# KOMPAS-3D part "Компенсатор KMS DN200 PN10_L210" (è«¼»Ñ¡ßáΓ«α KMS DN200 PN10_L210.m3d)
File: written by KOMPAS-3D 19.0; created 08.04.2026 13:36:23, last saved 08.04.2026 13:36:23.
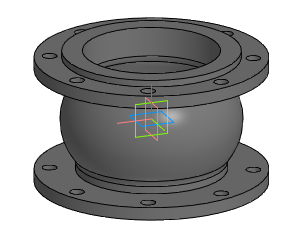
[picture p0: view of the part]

Document properties: Автор: Энергия; Полное имя файла: Z:\3.Личные\kachalov\3d для проектировщиков\7.1 Компенсатор\stp_Компенсатор KSM\Компенсатор KMS DN200 PN10_L210.m3d

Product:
- Part/product: Компенсатор KMS DN200 PN10_L210

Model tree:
1. Операция без истории:1  (labels: Компенсатор KMS DN200 PN10_L210)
